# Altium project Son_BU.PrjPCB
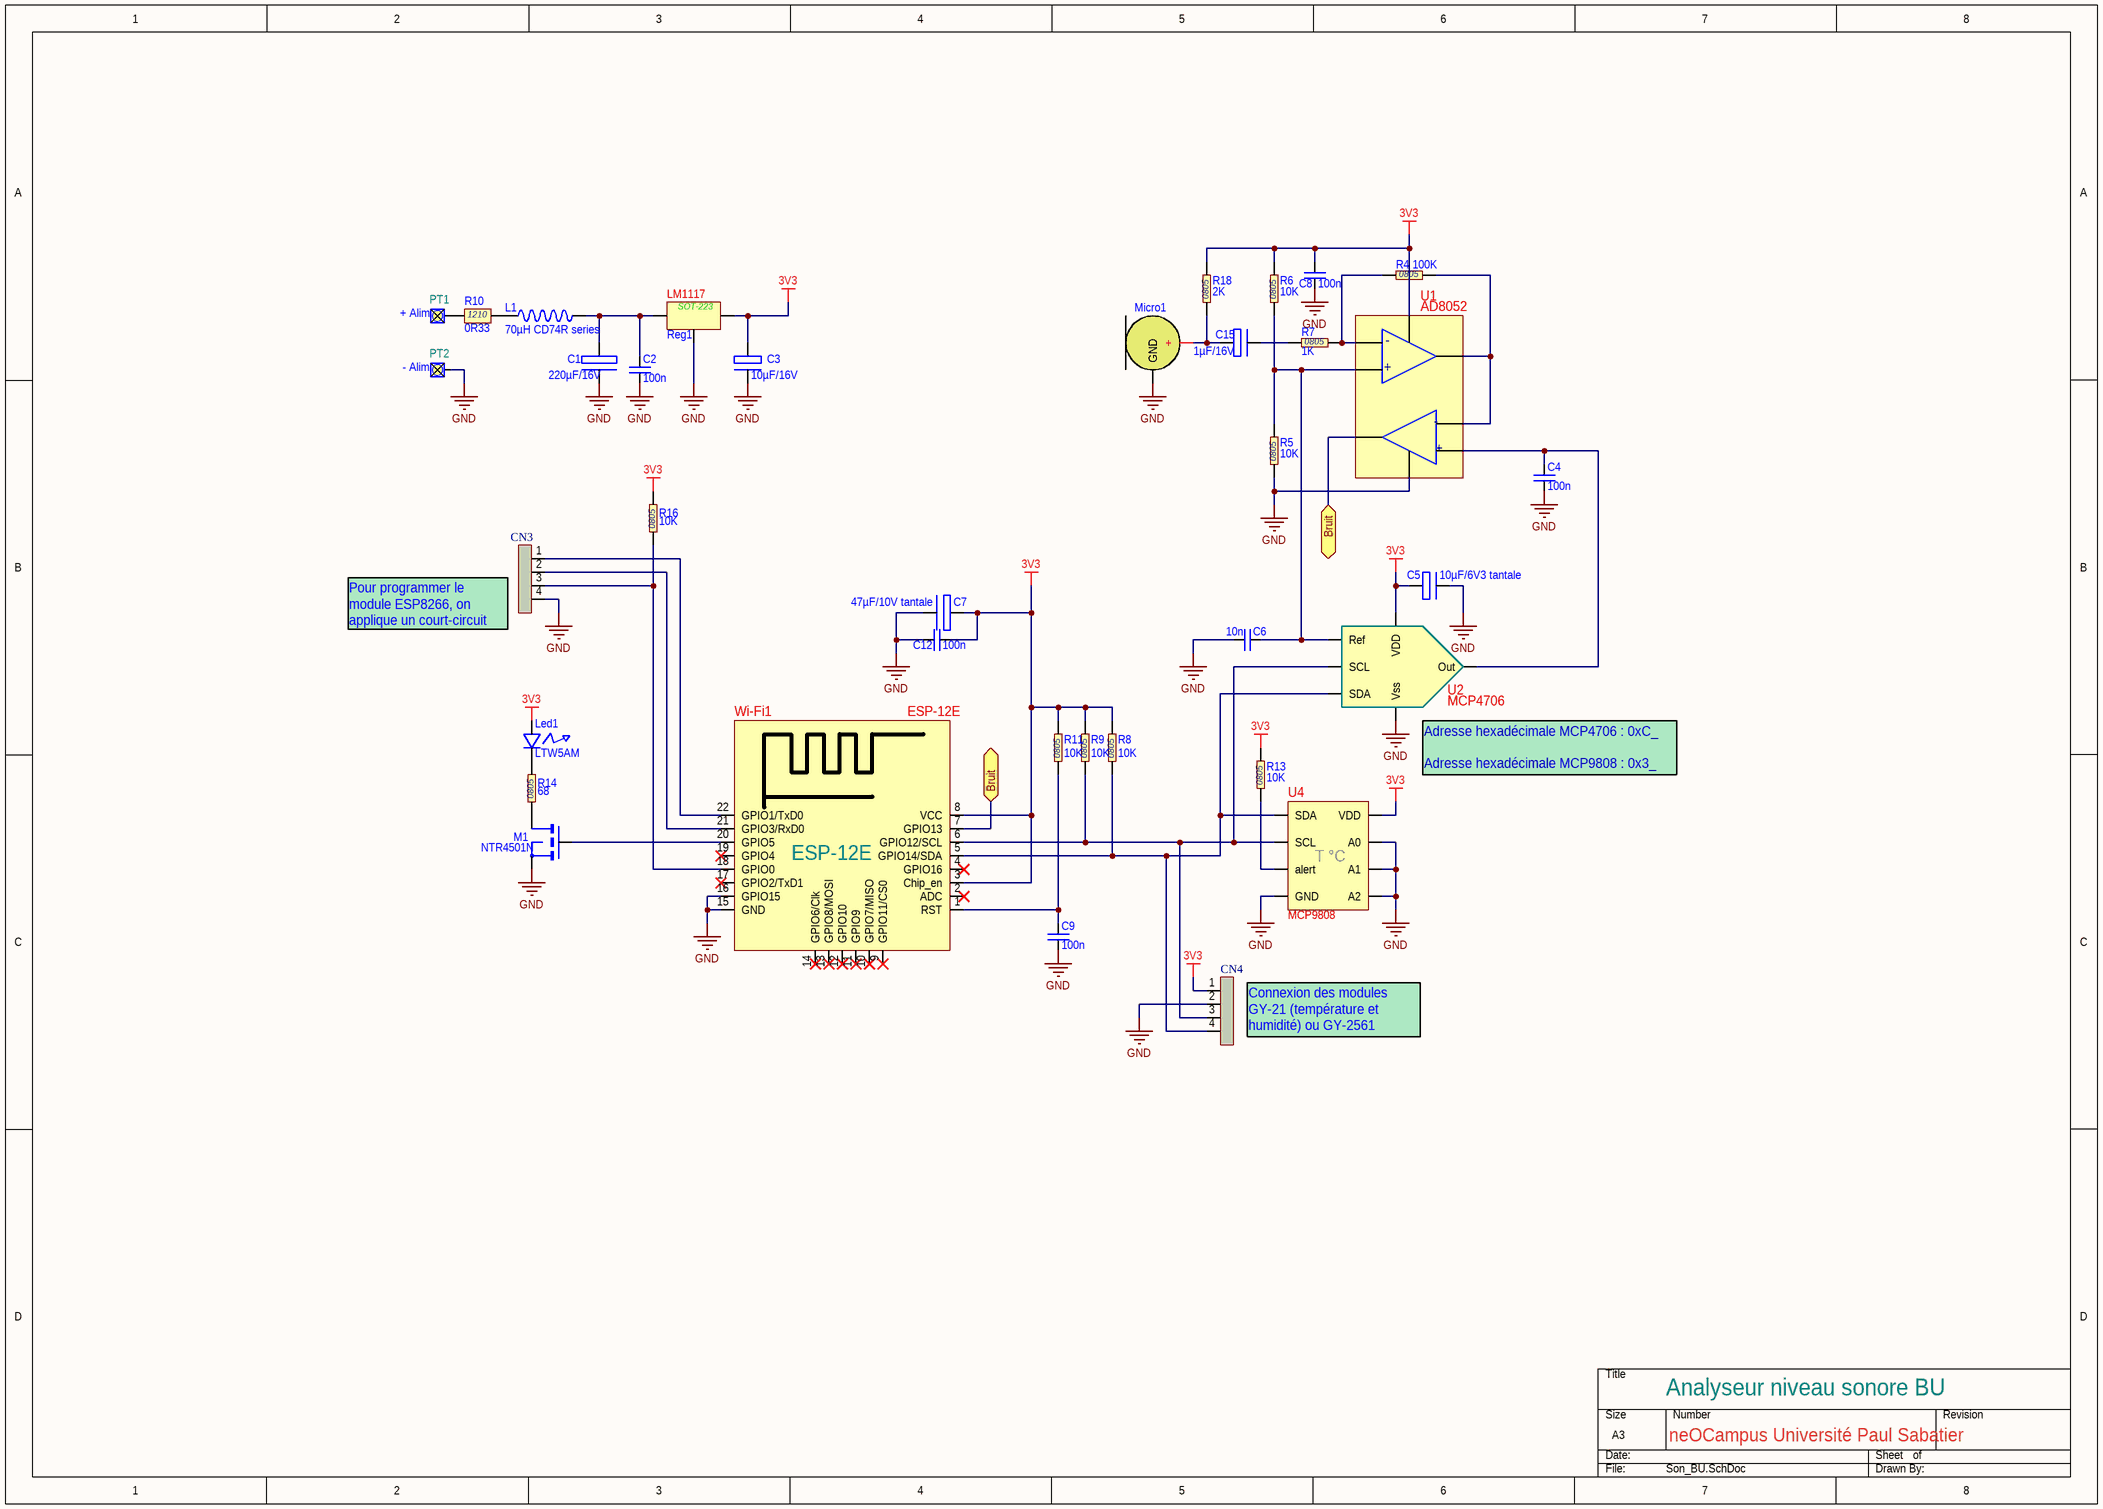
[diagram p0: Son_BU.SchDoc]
1 sheet, 36 parts. Net scope: flat (ports and power ports of the same name join across sheets).
Board file: Son_BU.PcbDoc

## Sheet Son_BU.SchDoc
size A3

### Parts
C1  220µF/16V  [7343-31]
C2  100n  [0805]
C3  10µF/16V  [Tantale 10µF/16V]
C4  100n  [0805]
C5  10µF/6V3 tantale  [Tantale 10µF/6V3]
C6  10n  [0805]
C7  47µF/10V tantale  [tantale 47µF/10V]
C8  100n  [0805]
C9  100n  [0805]
C12  100n  [0805]
C15  1µF/16V  [3216-18]
CN3  inch_ligne 1x4  [INCH_1x4_droit]  (value not drawn)
CN4  inch_ligne 1x4  [INCH_1x4_droit]  (value not drawn)
L1  70µH CD74R series  [SELF CD74R]
Led1  LTW5AM  [LTW5AM]
M1  NTR4501N  [SOT23 (NTR4501)]
Micro1  Electret  [Micro_electret simple]  (value not drawn)
PT1  + Alim  [Pointe de test]
PT2  - Alim  [Pointe de test]
R4  100K  [0805]
R5  10K  [0805]
R6  10K  [0805]
R7  1K  [0805]
R8  10K  [0805]
R9  10K  [0805]
R10  0R33  [1210]
R11  10K  [0805]
R13  10K  [0805]
R14  68  [0805]
R16  10K  [0805]
R18  2K  [0805]
Reg1  LM1117  [SOT223]
U1  AD8052  [SOIC08]
U2  MCP4706  [SOT23-6]
U4  MCP9808  [MSOP-08]
Wi-Fi1  ESP-12E  [ESP-12E]

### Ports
Bruit

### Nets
3V3: C3.1(V+) C5.1(V+) C7.1(V+) C8.2(CT2) C12.2(CT2) CN4.1 Led1.1(anode) R6.2(CT2) R8.2(CT2) R9.2(CT2) R11.2(CT2) R13.2(CT2) R16.2(CT2) R18.2(CT2) Reg1.2(OUT) U1.8(V+) U2.3(VDD) U4.8(VDD) Wi-Fi1.3(Chip_en) Wi-Fi1.8(VCC)
GND: C1.2(V-) C2.1(CT1) C3.2(V-) C4.1(CT1) C5.2(V-) C6.2(CT2) C7.2(V-) C8.1(CT1) C9.1(CT1) C12.1(CT1) CN3.4 CN4.2 M1.3(S) Micro1.0(GND) PT2.1(PIN) R5.1(CT1) Reg1.1(GND) U1.4(V-) U2.2(Vss) U4.4(GND) U4.5(A2) U4.6(A1) U4.7(A0) Wi-Fi1.15(GND) Wi-Fi1.16(GPIO15)
NetC1_1: C1.1(V+) C2.2(CT2) L1.1(CT1) Reg1.3(IN)
NetC4_2: C4.2(CT2) U1.5(in+) U2.1(Out)
NetC6_1: C6.1(CT1) R5.2(CT2) R6.1(CT1) U1.3(in+) U2.6(Ref)
NetC9_2: C9.2(CT2) R11.1(CT1) Wi-Fi1.1(RST)
NetC15_1: C15.1(V+) Micro1.1(+) R18.1(CT1)
NetC15_2: C15.2(V-) R7.1(CT1)
NetCN3_1: CN3.1 Wi-Fi1.22(GPIO1/TxD0)
NetCN3_2: CN3.2 Wi-Fi1.21(GPIO3/RxD0)
NetCN3_3: CN3.3 R16.1(CT1) Wi-Fi1.18(GPIO0)
NetCN4_3: CN4.3 R9.1(CT1) U2.5(SCL) U4.2(SCL) Wi-Fi1.6(GPIO12/SCL)
NetCN4_4: CN4.4 R8.1(CT1) U2.4(SDA) U4.1(SDA) Wi-Fi1.5(GPIO14/SDA)
NetL1_2: L1.2(CT2) R10.2(CT2)
NetLed1_2: Led1.2(cathode) R14.2(CT2)
NetM1_1: M1.1(D) R14.1(CT1)
NetM1_2: M1.2(G) Wi-Fi1.20(GPIO5)
NetPT1_1: PT1.1(PIN) R10.1(CT1)
NetR4_1: R4.1(CT1) R7.2(CT2) U1.2(in-)
NetR4_2: R4.2(CT2) U1.1(out) U1.6(in-)
NetR13_1: R13.1(CT1) U4.3(alert)
NetU1_7: U1.7(out) Wi-Fi1.7(GPIO13) ; port Bruit

Not connected (* = marked no-connect by the designer): Wi-Fi1 2(ADC)* 4(GPIO16)* 9(GPIO11/CS0)* 10(GPIO7/MISO)* 11(GPIO9)* 12(GPIO10)* 13(GPIO8/MOSI)* 14(GPIO6/Clk)* 17(GPIO2/TxD1)* 19(GPIO4)*

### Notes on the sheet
- (near CN3) Pour programmer le module ESP8266, on applique un court-circuit entre 3 et 4.
- (near U2) Adresse hexadécimale MCP4706 : 0xC_
  Adresse hexadécimale MCP9808 : 0x3_
- (near CN4) Connexion des modules GY-21 (température et humidité) ou GY-2561 (Luxmètre)
- Analyseur niveau sonore BU
- neOCampus Université Paul Sabatier

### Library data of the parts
C1 = tantale 220µF/16V: 253-5290 case 7343-31
C2 C4 C6 C8 C9 C12 = Cap_CMS_0805: CMS 0805
C3 = tantale 10µF/16V: 145-7461 case 3216-18
C5 = tantale 10µF/6V3: 175-4041 ou 145-7412 case 3216-18
C7 = tantale 47µF/10V: 175-4168
C15 = tantale 1µF/16V: 145-7406 case 3216-18
CN3 CN4 = Inch_1x4_droit
L1 = Self CD74R: SMT CD74R Aliexpress
Led1 = LTW5AM LED: LED Golden Dragon Plus
M1 = NTR4501N: MOSFET canal N
Micro1 = Microphone_03: Microphone électret
PT1 PT2 = PTEST: pointe de test CI 133-6225
R4-R9 R11 R13 R14 R16 R18 = Res CMS 0805: CMS 0805
R10 = Res CMS 1210 ERJ14B: CMS 1210
Reg1 = LM1117/800mA: Régulateur SOT-223
U1 = AD8052: AOP
U2 = MCP4706_1: DAC I2C (RS : 738-7111)
U4 = MCP9808: Digital temperature Sensor
Wi-Fi1 = ESP-12E: ESP-12E module Wi-Fi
